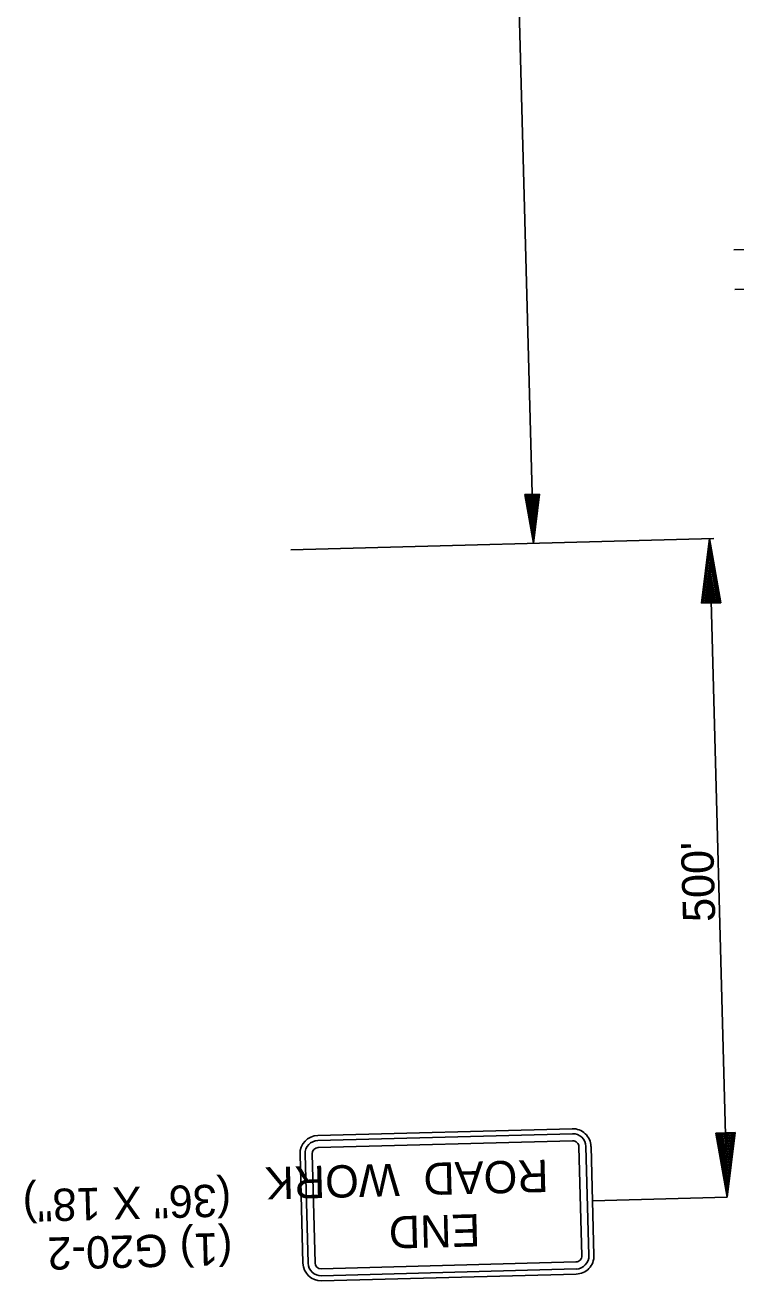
# Model space of a CAD drawing. Extents: x 1930579 to 1931593, y 596452 to 598537.
# Drawn here: x 1930730.8 to 1930862.7, y 597593.4 to 597826.5 of the extents above; entities that cross this region are included whole.
import ezdxf

# ---------------------------------------------------------------- set-up
doc = ezdxf.new("R2010")
doc.units = 0
for name, color, linetype in [('P_TC_Signs_Temporary', 7, 'Continuous'), ('R_Annotation', 7, 'Continuous'), ('R_Draft', 7, 'Continuous')]:
    doc.layers.add(name, color=color, linetype=linetype)

msp = doc.modelspace()

# ---------------------------------------------------------------- linework, layer by layer
at = {"layer": 'P_TC_Signs_Temporary'}
for p, q in [((1930832.31, 597621.61), (1930785.08, 597620.34)), ((1930832.34, 597620.67), (1930785.1, 597619.41)), ((1930832.37, 597619.36), (1930785.14, 597618.09)), ((1930835.38, 597598.06), (1930834.84, 597618.3)), ((1930836.32, 597598.08), (1930835.78, 597618.33)), ((1930781.8, 597616.88), (1930782.34, 597596.64)), ((1930782.73, 597616.9), (1930783.28, 597596.66)), ((1930784.05, 597616.94), (1930784.59, 597596.7)), ((1930834.07, 597598.02), (1930833.53, 597618.27)), ((1930785.74, 597595.6), (1930832.98, 597596.87)), ((1930785.78, 597594.29), (1930833.01, 597595.56)), ((1930785.8, 597593.35), (1930833.04, 597594.62))]:
    msp.add_line(p, q, dxfattribs=at)
for centre, radius, start, end in [((1930832.4, 597618.24), 3.37, 1.5377, 91.5377), ((1930832.4, 597618.24), 2.44, 1.5377, 91.5377), ((1930785.17, 597616.97), 3.38, 91.5377, 181.5377), ((1930785.17, 597616.97), 2.44, 91.5377, 181.5377), ((1930832.4, 597618.24), 1.13, 1.5377, 91.5377), ((1930785.17, 597616.97), 1.13, 91.5377, 181.5377), ((1930832.95, 597597.99), 1.13, 271.5377, 1.5377), ((1930832.95, 597597.99), 2.44, 271.5377, 1.5377), ((1930832.95, 597597.99), 3.38, 271.5377, 1.5377), ((1930785.71, 597596.73), 3.37, 181.5377, 271.5377), ((1930785.71, 597596.73), 2.44, 181.5377, 271.5377), ((1930785.71, 597596.73), 1.13, 181.5377, 271.5377)]:
    msp.add_arc(centre, radius, start, end, dxfattribs=at)
at = {"layer": 'R_Draft'}
for p, q in [((1930816.84, 598038.34), (1930825.1, 597730.33)), ((1930910.32, 597786.09), (1930862.28, 597784.8)), ((1930911.04, 597778.74), (1930862.48, 597777.44)), ((1930826.22, 597739.43), (1930823.5, 597739.36)), ((1930823.5, 597739.36), (1930825.1, 597730.33)), ((1930823.73, 597739.36), (1930825.06, 597731.84)), ((1930823.96, 597739.37), (1930825.02, 597733.4)), ((1930824.19, 597739.37), (1930824.98, 597734.91)), ((1930824.42, 597739.38), (1930824.94, 597736.45)), ((1930824.65, 597739.39), (1930824.9, 597737.96)), ((1930825.07, 597739.4), (1930824.9, 597737.96)), ((1930825.3, 597739.4), (1930824.94, 597736.45)), ((1930825.54, 597739.41), (1930824.98, 597734.91)), ((1930825.76, 597739.42), (1930825.02, 597733.4)), ((1930825.99, 597739.42), (1930825.06, 597731.84)), ((1930826.22, 597739.43), (1930825.1, 597730.33)), ((1930858.56, 597731.23), (1930780.06, 597729.12)), ((1930856.28, 597719.19), (1930857.76, 597731.2)), ((1930857.76, 597731.2), (1930861.04, 597608.88)), ((1930859.87, 597719.29), (1930857.76, 597731.2)), ((1930856.58, 597719.2), (1930857.81, 597729.21)), ((1930859.57, 597719.28), (1930857.81, 597729.21)), ((1930856.89, 597719.21), (1930857.87, 597727.15)), ((1930859.27, 597719.27), (1930857.87, 597727.15)), ((1930857.19, 597719.22), (1930857.92, 597725.15)), ((1930858.97, 597719.26), (1930857.92, 597725.15)), ((1930857.5, 597719.22), (1930857.97, 597723.13)), ((1930857.8, 597719.23), (1930858.03, 597721.13)), ((1930858.66, 597719.26), (1930857.97, 597723.13)), ((1930858.36, 597719.25), (1930858.03, 597721.13)), ((1930856.28, 597719.19), (1930859.87, 597719.29)), ((1930862.52, 597620.89), (1930858.93, 597620.79)), ((1930858.93, 597620.79), (1930861.04, 597608.88)), ((1930859.22, 597620.8), (1930860.99, 597610.88)), ((1930859.53, 597620.81), (1930860.93, 597612.93)), ((1930859.83, 597620.82), (1930860.88, 597614.92)), ((1930860.14, 597620.83), (1930860.82, 597616.95)), ((1930860.44, 597620.83), (1930860.77, 597618.95)), ((1930861, 597620.85), (1930860.77, 597618.95)), ((1930861.3, 597620.86), (1930860.82, 597616.95)), ((1930861.61, 597620.87), (1930860.88, 597614.92)), ((1930861.91, 597620.87), (1930860.93, 597612.93)), ((1930862.22, 597620.88), (1930860.99, 597610.88)), ((1930862.52, 597620.89), (1930861.04, 597608.88)), ((1930836.05, 597608.21), (1930861.04, 597608.88))]:
    msp.add_line(p, q, dxfattribs=at)

# ---------------------------------------------------------------- texts
at = {"layer": 'P_TC_Signs_Temporary'}
for s, p in [('ROAD  WORK', (1930827.8, 597615.86)), ('END', (1930815.14, 597605.77))]:
    msp.add_text(s, height=6, rotation=181.5377, dxfattribs=at).set_placement(p)
at = {"layer": 'R_Annotation'}
for s, p in [('(36" X 18")', (1930768.95, 597611.32)), ('(1) G20-2', (1930769.19, 597602.32))]:
    msp.add_text(s, height=6, rotation=181.5377, dxfattribs=at).set_placement(p)
at = {"layer": 'R_Draft'}
msp.add_text("500'", height=6, rotation=91.5377, dxfattribs=at).set_placement((1930858.85, 597660.07))

doc.saveas('drawing.dxf')
